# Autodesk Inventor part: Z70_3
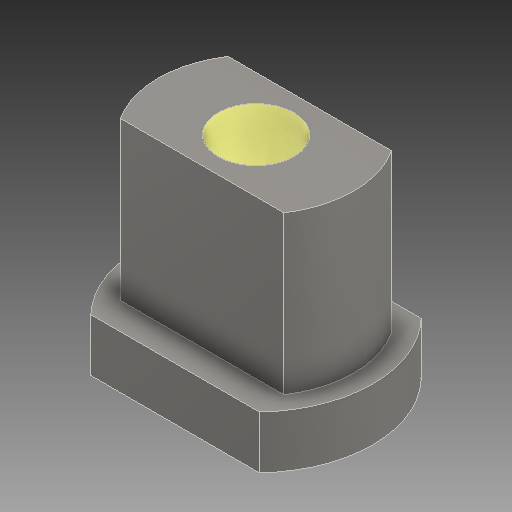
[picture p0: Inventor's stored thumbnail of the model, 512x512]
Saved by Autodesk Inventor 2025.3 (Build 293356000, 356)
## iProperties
Created: 2025-03
Part Number: Z70_3
Material: Všeobecné
Document SubType Name: Modeling
Designer: Patrik
Density: 1 g/cm^3
Appearance: Výchozí
Mass: 24.965 g
Surface Area: 79.3366 cm^2
Volume: 24.965 cm^3
Author: Patrik
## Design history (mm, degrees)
feature "Base1"
node "Těleso1"
